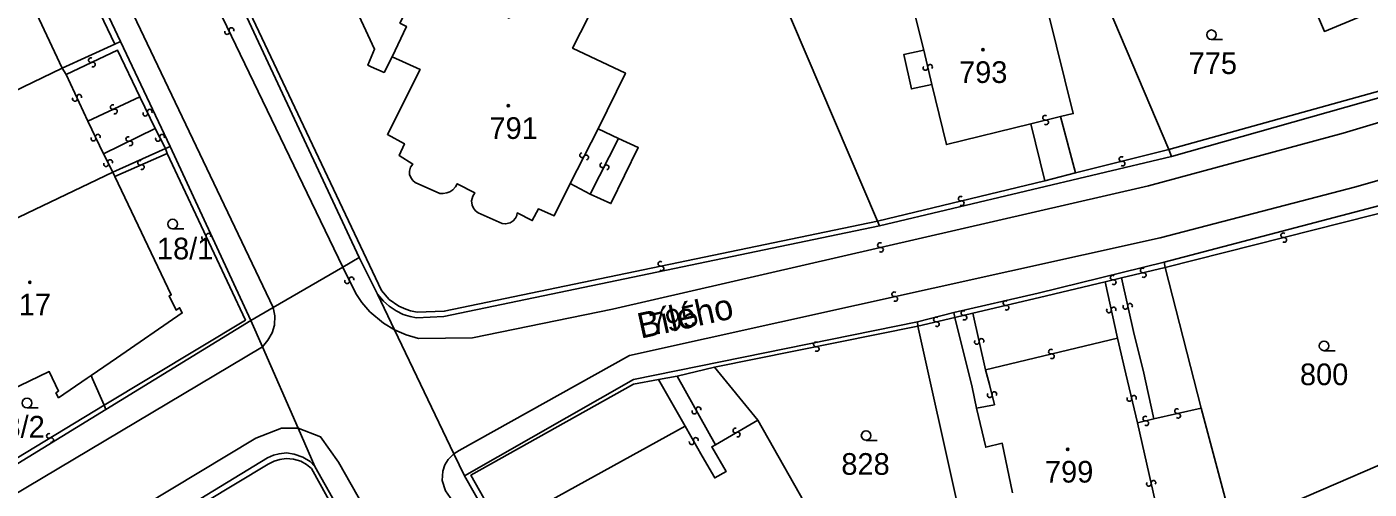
# Model space of a CAD drawing. Extents: x -600391 to -599491, y -1160176 to -1159402.
# Drawn here: x -600056.6 to -599951.3, y -1160105.5 to -1160069.3 of the extents above; entities that cross this region are included whole.
import ezdxf

# ---------------------------------------------------------------- set-up
doc = ezdxf.new("R2010")
doc.units = 0
for name, color, linetype in [('Level 1', 7, 'Continuous'), ('Level 11', 7, 'Continuous'), ('Level 13', 7, 'Continuous'), ('Level 3', 7, 'Continuous'), ('Level 4', 7, 'Continuous'), ('Level 5', 7, 'Continuous')]:
    doc.layers.add(name, color=color, linetype=linetype)

msp = doc.modelspace()

# ---------------------------------------------------------------- linework, layer by layer
at = {"layer": 'Level 1'}
for points in [[(-600006.64, -1160045.18), (-599989.86, -1160084.51)], [(-600027.94, -1160071.62), (-600028.57, -1160072.85), (-600029.57, -1160072.4), (-600029.83, -1160072.28), (-600029.31, -1160071.03), (-600033.81, -1160061.32), (-600032.1, -1160060.51), (-600032.98, -1160058.36)], [(-599958.56, -1160060.36), (-599956.78, -1160064.28), (-599957.06, -1160064.35), (-599954.81, -1160069.63), (-599951.85, -1160068.41)], [(-600053.12, -1160062.22), (-600049.24, -1160070.42)], [(-600041.96, -1160062.84), (-600030.51, -1160087.37)], [(-600025.52, -1160065.4), (-600018.76, -1160068.58), (-600017.51, -1160066.07), (-600012.52, -1160068.49), (-600013.78, -1160070.93), (-600009.63, -1160072.89), (-600011.77, -1160077.27)], [(-599986.23, -1160071.1), (-599987.04, -1160067.89), (-599977.13, -1160065.47), (-599974.51, -1160076.07), (-599975.5, -1160076.3)], [(-599972.3, -1160066.44), (-599967.02, -1160078.9)], [(-600053.82, -1160072.51), (-600049.69, -1160070.63)], [(-600049.69, -1160070.63), (-600049.24, -1160070.42)], [(-600049.24, -1160070.42), (-600045.35, -1160078.66)], [(-599966.81, -1160079.43), (-599932.7, -1160069.8)], [(-600013.97, -1160081.57), (-600015.23, -1160084.1), (-600016.46, -1160083.55), (-600016.94, -1160084.47), (-600018.12, -1160083.87), (-600018.16, -1160084.08), (-600018.26, -1160084.29), (-600018.43, -1160084.49), (-600018.67, -1160084.65), (-600019.03, -1160084.73), (-600019.31, -1160084.7), (-600021.19, -1160083.87), (-600021.4, -1160083.7), (-600021.56, -1160083.5), (-600021.66, -1160083.25), (-600021.7, -1160082.91), (-600021.61, -1160082.55), (-600021.45, -1160082.29), (-600022.83, -1160081.58), (-600022.96, -1160081.82), (-600023.18, -1160082.06), (-600023.41, -1160082.21), (-600023.63, -1160082.3), (-600023.93, -1160082.35), (-600024.18, -1160082.33), (-600026.12, -1160081.47), (-600026.32, -1160081.31), (-600026.47, -1160081.1), (-600026.56, -1160080.85), (-600026.57, -1160080.6), (-600026.48, -1160080.27), (-600026.31, -1160080.04), (-600027.38, -1160079.37), (-600026.97, -1160078.44), (-600028.3, -1160077.71), (-600025.74, -1160072.61), (-600027.94, -1160071.62)], [(-599985.6, -1160073.8), (-599987.21, -1160074.14), (-599987.8, -1160071.45), (-599986.23, -1160071.1)], [(-600065.43, -1160078.11), (-600053.82, -1160072.51)], [(-599977.85, -1160076.87), (-599984.46, -1160078.5), (-599985.6, -1160073.8)], [(-599976.74, -1160081.35), (-599977.85, -1160076.87)], [(-599975.5, -1160076.3), (-599974.33, -1160080.73)], [(-600010.17, -1160078.02), (-600008.63, -1160078.74), (-600010.77, -1160083.13), (-600012.39, -1160082.4)], [(-600011.77, -1160077.27), (-600010.17, -1160078.02)], [(-600049.84, -1160080.67), (-600045.71, -1160078.82)], [(-600045.71, -1160078.82), (-600045.35, -1160078.66)], [(-600045.35, -1160078.66), (-600039.01, -1160092.3)], [(-599967.02, -1160078.9), (-599966.81, -1160079.43)], [(-599989.71, -1160084.88), (-599966.81, -1160079.43)], [(-600060.91, -1160085.95), (-600049.84, -1160080.67)], [(-600051.55, -1160096.62), (-600049.56, -1160095.25), (-600044.39, -1160091.71), (-600044.61, -1160091.31), (-600044.88, -1160091.49), (-600045.41, -1160090.37), (-600045.26, -1160090.3), (-600049.69, -1160081.01)], [(-600049.84, -1160080.67), (-600049.69, -1160081.01)], [(-599974.33, -1160080.73), (-599976.74, -1160081.35)], [(-600012.39, -1160082.4), (-600013.97, -1160081.57)], [(-599967.37, -1160087.73), (-599948.86, -1160082.86)], [(-600029.07, -1160090.25), (-600028.62, -1160090.79), (-600028.17, -1160091.19), (-600027.62, -1160091.56), (-600027.06, -1160091.83), (-600026.53, -1160091.99), (-600026.02, -1160092.09), (-600023.89, -1160092), (-599989.71, -1160084.88)], [(-599989.86, -1160084.51), (-599989.71, -1160084.88)], [(-600031.79, -1160088.11), (-600030.51, -1160087.37)], [(-600030.51, -1160087.37), (-600029.07, -1160090.25)], [(-600037.27, -1160091.29), (-600031.79, -1160088.11)], [(-599983.88, -1160091.69), (-599977.26, -1160090.16), (-599967.37, -1160087.73)], [(-599967.37, -1160087.73), (-599967.31, -1160088.16)], [(-599967.31, -1160088.16), (-599964.48, -1160099.18)], [(-600029.07, -1160090.25), (-600027.74, -1160093.03)], [(-600064.95, -1160091.88), (-600063.13, -1160091), (-600059.45, -1160098.53), (-600054.83, -1160096.31), (-600054.09, -1160097.84), (-600054.31, -1160097.99), (-600054.09, -1160098.36), (-600051.86, -1160096.84), (-600051.55, -1160096.62)], [(-600039.01, -1160092.3), (-600037.27, -1160091.29)], [(-599986.74, -1160092.4), (-599983.88, -1160091.69)], [(-599983.88, -1160091.69), (-599983.79, -1160092.07)], [(-600050.39, -1160099.28), (-600039.01, -1160092.3)], [(-600038.1, -1160094.38), (-600039.01, -1160092.3)], [(-600022.27, -1160104.48), (-600008.99, -1160096.93), (-599986.74, -1160092.4)], [(-599986.69, -1160092.75), (-599986.74, -1160092.4)], [(-599983.59, -1160106.73), (-599986.69, -1160092.75)], [(-599983.79, -1160092.07), (-599982.44, -1160097.54), (-599982.09, -1160099.18)], [(-600027.74, -1160093.03), (-600023.09, -1160102.76)], [(-600035.3, -1160100.76), (-600038.1, -1160094.38)], [(-600051.55, -1160096.62), (-600051.44, -1160096.88), (-600050.53, -1160098.96)], [(-600007.05, -1160096.93), (-600005.57, -1160096.66)], [(-600004.95, -1160100.6), (-600007.05, -1160096.93)], [(-600005.57, -1160096.66), (-600002.65, -1160095.96)], [(-599999.26, -1160100.13), (-600002.65, -1160095.96)], [(-600050.53, -1160098.96), (-600050.39, -1160099.28)], [(-600058.81, -1160104.45), (-600050.39, -1160099.28)], [(-599999.26, -1160100.13), (-599994.78, -1160108.03), (-600000.45, -1160111.2), (-600001.17, -1160109.91), (-600010.56, -1160115.34), (-600015.61, -1160106.47), (-600004.95, -1160100.6)], [(-599982.09, -1160099.18), (-599981.37, -1160102.25), (-599980.08, -1160101.94), (-599979.27, -1160105.83)], [(-599964.48, -1160099.18), (-599961.96, -1160108.61)], [(-600033.99, -1160103.75), (-600035.3, -1160100.76)], [(-599942.6, -1160100.22), (-599961.96, -1160108.61)], [(-600047.7, -1160109.17), (-600037.71, -1160103.09), (-600037.23, -1160102.88), (-600036.8, -1160102.76), (-600036.21, -1160102.7), (-600035.62, -1160102.78), (-600034.93, -1160103.02), (-600034.37, -1160103.37), (-600033.99, -1160103.75)], [(-600023.09, -1160102.76), (-600022.27, -1160104.48)], [(-600033.99, -1160103.75), (-600015.67, -1160136.28)], [(-600011.85, -1160122.8), (-600022.27, -1160104.48)]]:
    msp.add_lwpolyline(points, dxfattribs=at)
at = {"layer": 'Level 13'}
for centre, start, end in [((-600040.88, -1160069.68), 153.1022, 25.2002), ((-600040.54, -1160069.52), 332.8878, 205.4778), ((-600051.56, -1160071.88), 62.6699, 294.7679), ((-600051.4, -1160072.22), 242.4554, 115.0454), ((-599986.1, -1160072.49), 140.5068, 12.6048), ((-599985.74, -1160072.41), 320.2923, 192.8823), ((-600052.81, -1160074.92), 151.9532, 24.5432), ((-600052.47, -1160074.76), 332.1676, 204.2656), ((-600049.84, -1160075.56), 62.5128, 294.6108), ((-600049.68, -1160075.9), 242.2984, 114.8884), ((-600046.95, -1160075.92), 333.0966, 205.1946), ((-600047.29, -1160076.08), 152.8822, 25.4722), ((-599976.72, -1160076.4), 50.7923, 283.3823), ((-599976.64, -1160076.76), 231.0067, 103.1047), ((-600051.36, -1160078.04), 152.4563, 25.0463), ((-600051.02, -1160077.88), 332.6708, 204.7688), ((-600048.63, -1160078.07), 63.4397, 296.0297), ((-600046.3, -1160078.06), 154.9653, 27.5553), ((-600045.98, -1160077.89), 335.1798, 207.2778), ((-600048.47, -1160078.41), 243.6541, 115.7521), ((-600050.37, -1160080.04), 154.5191, 27.1091), ((-600050.05, -1160079.88), 334.7335, 206.8315), ((-600047.7, -1160079.93), 61.0896, 293.1876), ((-600047.56, -1160080.27), 240.8751, 113.4651), ((-600013.03, -1160079.34), 100.0627, 332.6527), ((-600012.71, -1160079.51), 280.2772, 152.3752), ((-600011.44, -1160080.13), 100.2801, 332.8701), ((-600011.12, -1160080.29), 280.4946, 152.5926), ((-599970.72, -1160079.64), 51.213, 283.803), ((-599970.64, -1160080), 231.4274, 103.5254), ((-599983.34, -1160082.75), 50.7003, 283.2903), ((-599983.26, -1160083.11), 230.9147, 103.0127), ((-600042.68, -1160085.81), 152.2855, 24.8755), ((-600042.34, -1160085.65), 332.4999, 204.5979), ((-599989.67, -1160086.39), 50.3335, 282.4315), ((-599958.04, -1160085.62), 51.5682, 283.6661), ((-599957.96, -1160085.98), 231.3537, 103.9437), ((-599989.59, -1160086.75), 230.1191, 102.7091), ((-600006.89, -1160087.86), 48.9118, 281.5018), ((-600006.81, -1160088.22), 229.1262, 101.2242), ((-599969.06, -1160088.38), 50.6973, 282.7953), ((-599968.98, -1160088.74), 230.4828, 103.0728), ((-600031.46, -1160089.23), 152.8351, 25.4251), ((-600031.12, -1160089.07), 333.0496, 205.1475), ((-599971.42, -1160088.94), 50.8853, 282.9833), ((-599971.34, -1160089.3), 230.6708, 103.2608), ((-599988.55, -1160090.25), 49.6492, 282.2392), ((-599988.47, -1160090.61), 229.8636, 101.9616), ((-599983.13, -1160091.72), 51.0232, 283.1212), ((-599979.82, -1160090.94), 50.6316, 282.7296), ((-599979.74, -1160091.3), 230.4172, 103.0072), ((-599971.71, -1160091.52), 139.9015, 11.9995), ((-599971.35, -1160091.44), 319.6871, 192.2771), ((-599970.42, -1160091.23), 139.9425, 12.0405), ((-599970.06, -1160091.15), 319.7281, 192.3181), ((-599985.28, -1160092.23), 50.5692, 282.6672), ((-599985.2, -1160092.59), 230.3547, 102.9447), ((-599983.05, -1160092.08), 230.8087, 103.3987), ((-599981.71, -1160093.91), 320.0654, 192.1634), ((-599994.7, -1160094.18), 48.7448, 280.8428), ((-599994.63, -1160094.54), 228.5303, 101.1203), ((-599982.07, -1160093.99), 139.8509, 12.4409), ((-599976.26, -1160094.75), 50.8475, 282.9455), ((-599976.18, -1160095.11), 230.6331, 103.2231), ((-599980.7, -1160098.08), 320.9399, 193.5299), ((-600003.91, -1160099.27), 336.1768, 208.7668), ((-599981.06, -1160098.16), 141.1543, 13.2523), ((-599970.11, -1160098.46), 140.5238, 13.1138), ((-599969.75, -1160098.38), 320.7383, 192.8363), ((-600004.23, -1160099.45), 156.3912, 28.4892), ((-599968.86, -1160100), 50.2502, 282.8402), ((-599966.37, -1160099.42), 50.0963, 282.6863), ((-599966.29, -1160099.78), 230.3108, 102.4088), ((-600054.85, -1160101.36), 68.291, 300.881), ((-600001.01, -1160100.93), 67.1996, 299.7896), ((-600000.83, -1160101.25), 247.4141, 119.5121), ((-599968.78, -1160100.36), 230.4646, 102.5626), ((-600054.67, -1160101.68), 248.5055, 120.6035), ((-600004.44, -1160101.86), 156.8506, 29.4406), ((-600004.12, -1160101.68), 337.0651, 209.1631), ((-599968.58, -1160105.12), 139.9104, 12.5004), ((-599968.22, -1160105.04), 320.1249, 192.2229)]:
    msp.add_arc(centre, 0.184, start, end, dxfattribs=at)
at = {"layer": 'Level 3'}
for points in [[(-600037.27, -1160091.29), (-600057.56, -1160048.75), (-600077.92, -1160005.83), (-600078.21, -1160005.38), (-600078.52, -1160005.04), (-600078.89, -1160004.78), (-600079.31, -1160004.57), (-600079.97, -1160004.4), (-600080.6, -1160004.42)], [(-600031.79, -1160088.11), (-600049.63, -1160051.09), (-600056.12, -1160037.4), (-600056.33, -1160036.93), (-600056.42, -1160036.47), (-600056.41, -1160035.97), (-600056.25, -1160035.39), (-600055.93, -1160034.88), (-600055.58, -1160034.55), (-600055.38, -1160034.38)], [(-599967.02, -1160078.9), (-599933.24, -1160069.5), (-599940.38, -1160052.87)], [(-600057.43, -1160064.8), (-600053.38, -1160062.9), (-600049.69, -1160070.63)], [(-599989.86, -1160084.51), (-600023.84, -1160091.58), (-600025.96, -1160091.65), (-600026.48, -1160091.54), (-600026.86, -1160091.42), (-600027.4, -1160091.19), (-600028.16, -1160090.66), (-600028.78, -1160089.96), (-600041.68, -1160062.64)], [(-600057.43, -1160064.8), (-600053.82, -1160072.51)], [(-600027.94, -1160071.62), (-600026.81, -1160069.24), (-600027.32, -1160068.98), (-600025.52, -1160065.4)], [(-600053.49, -1160073), (-600049.47, -1160071.1), (-600047.72, -1160074.77)], [(-600027.74, -1160093.03), (-600026.82, -1160093.42), (-600025.86, -1160093.71), (-600021.64, -1160093.67), (-600010.66, -1160091.41), (-599968.6, -1160081.73), (-599953.35, -1160077.6), (-599932.07, -1160071.24)], [(-599985.6, -1160073.8), (-599986.23, -1160071.1)], [(-600053.82, -1160072.51), (-600053.49, -1160073)], [(-600053.49, -1160073), (-600051.79, -1160076.68)], [(-600051.79, -1160076.68), (-600047.72, -1160074.77)], [(-600047.72, -1160074.77), (-600046.53, -1160077.24)], [(-599930.21, -1160075.52), (-599930.99, -1160075.71), (-599952.34, -1160081.82), (-599967.7, -1160085.82), (-600009.32, -1160095.04), (-600022.67, -1160102.5), (-600023.09, -1160102.76)], [(-600051.79, -1160076.68), (-600050.58, -1160079.24)], [(-599975.5, -1160076.3), (-599977.85, -1160076.87)], [(-600046.53, -1160077.24), (-600050.58, -1160079.24)], [(-600046.53, -1160077.24), (-600045.76, -1160078.7), (-600045.71, -1160078.82)], [(-600011.77, -1160077.27), (-600013.97, -1160081.57)], [(-600010.17, -1160078.02), (-600012.39, -1160082.4)], [(-600045.71, -1160078.82), (-600045.57, -1160079.2)], [(-599967.02, -1160078.9), (-599974.33, -1160080.73)], [(-600050.58, -1160079.24), (-600049.84, -1160080.67)], [(-600045.57, -1160079.2), (-600039.44, -1160092.27), (-600050.53, -1160098.96)], [(-600049.69, -1160081.01), (-600045.57, -1160079.2)], [(-599976.74, -1160081.35), (-599989.86, -1160084.51)], [(-599967.31, -1160088.16), (-599948.69, -1160083.45)], [(-600031.79, -1160088.11), (-600030.79, -1160090.19), (-600030.3, -1160090.9), (-600029.67, -1160091.62), (-600028.6, -1160092.51), (-600027.74, -1160093.03)], [(-599970.73, -1160088.97), (-599967.31, -1160088.16)], [(-599982.39, -1160091.73), (-599977.17, -1160090.5), (-599972.02, -1160089.28)], [(-599972.02, -1160089.28), (-599970.73, -1160088.97)], [(-599971.04, -1160093.69), (-599972.02, -1160089.28)], [(-599968.18, -1160100.03), (-599969.04, -1160096.21), (-599969.74, -1160093.41), (-599970.73, -1160088.97)], [(-600037.27, -1160091.29), (-600037.13, -1160091.93), (-600037.17, -1160092.67), (-600037.35, -1160093.27), (-600037.67, -1160093.86), (-600038.1, -1160094.38)], [(-600002.65, -1160095.96), (-599986.69, -1160092.75)], [(-599986.69, -1160092.75), (-599983.79, -1160092.07)], [(-599983.79, -1160092.07), (-599982.39, -1160091.73)], [(-599982.39, -1160091.73), (-599981.39, -1160096.17)], [(-599981.39, -1160096.17), (-599971.04, -1160093.69)], [(-599971.04, -1160093.69), (-599970.38, -1160096.5), (-599969.47, -1160100.33)], [(-600038.1, -1160094.38), (-600078.93, -1160118.69), (-600104.94, -1160134.34), (-600126.03, -1160147.1), (-600155.88, -1160165.42)], [(-600011.5, -1160122.58), (-600021.76, -1160104.45), (-600009, -1160097.3), (-600007.05, -1160096.93)], [(-600002.58, -1160102.05), (-600005.57, -1160096.66)], [(-599982.09, -1160099.18), (-599980.69, -1160098.92), (-599981.08, -1160097.33), (-599981.39, -1160096.17)], [(-600050.53, -1160098.96), (-600058.99, -1160104.07)], [(-599999.26, -1160100.13), (-600002.58, -1160102.05)], [(-599968.18, -1160100.03), (-599969.47, -1160100.33)], [(-599964.48, -1160099.18), (-599968.18, -1160100.03)], [(-600035.3, -1160100.76), (-600036.62, -1160100.76), (-600038.63, -1160101.53), (-600104, -1160140.93), (-600152.12, -1160170.19)], [(-600035.3, -1160100.76), (-600033.55, -1160101.43), (-600032.15, -1160103.43), (-600003.04, -1160154.73), (-599996.06, -1160167.09), (-599995.71, -1160167.83), (-599995.54, -1160168.65), (-599995.53, -1160169.34), (-599995.66, -1160170.19), (-599996.01, -1160171)], [(-600004.95, -1160100.6), (-600003.61, -1160102.95), (-600002.63, -1160104.65), (-600001.74, -1160104.16), (-600002.86, -1160102.21), (-600002.58, -1160102.05)], [(-599969.47, -1160100.33), (-599967.32, -1160109.83)], [(-600047.52, -1160109.52), (-600037.65, -1160103.57), (-600037.18, -1160103.33), (-600036.75, -1160103.2), (-600036.25, -1160103.14), (-600035.68, -1160103.18), (-600035.1, -1160103.35), (-600034.65, -1160103.6), (-600034.26, -1160103.91), (-600031.11, -1160109.58)], [(-599983.69, -1160176.08), (-599996.95, -1160152.06), (-600023.38, -1160106.19), (-600023.76, -1160105.67), (-600024, -1160104.87), (-600023.96, -1160104.12), (-600023.8, -1160103.64), (-600023.54, -1160103.22), (-600023.09, -1160102.76)]]:
    msp.add_lwpolyline(points, dxfattribs=at)
at = {"layer": 'Level 5'}
for p, q in [((-599963.67, -1160070.27), (-599962.8, -1160070.27)), ((-600045.15, -1160085.12), (-600044.28, -1160085.12)), ((-599954.84, -1160094.68), (-599953.96, -1160094.68)), ((-600056.57, -1160099.16), (-600055.7, -1160099.16)), ((-599990.76, -1160101.71), (-599989.89, -1160101.71))]:
    msp.add_line(p, q, dxfattribs=at)
for centre, radius in [((-599963.67, -1160069.89), 0.375), ((-599981.6, -1160071.07), 0.09), ((-599981.6, -1160071.07), 0.0521), ((-600018.82, -1160075.46), 0.09), ((-600018.82, -1160075.46), 0.0521), ((-600045.15, -1160084.74), 0.375), ((-600056.35, -1160089.31), 0.09), ((-600056.35, -1160089.31), 0.0521), ((-599954.84, -1160094.3), 0.375), ((-600056.57, -1160098.78), 0.375), ((-599990.76, -1160101.33), 0.375), ((-599974.94, -1160102.42), 0.09), ((-599974.94, -1160102.42), 0.0521)]:
    msp.add_circle(centre, radius, dxfattribs=at)

# ---------------------------------------------------------------- texts
at = {"layer": 'Level 11'}
msp.add_text('Bílého', height=2, rotation=12.3997, dxfattribs=at).set_placement((-600008.44, -1160093.74))
at = {"layer": 'Level 4'}
for s, p in [('775', (-599965.46, -1160072.97)), ('793', (-599983.47, -1160073.67)), ('791', (-600020.3, -1160078.06)), ('18/1', (-600046.38, -1160087.51)), ('17', (-600057.22, -1160091.91)), ('800', (-599956.73, -1160097.38)), ('18/2', (-600059.6, -1160101.49)), ('828', (-599992.7, -1160104.41)), ('799', (-599976.73, -1160105.02))]:
    msp.add_text(s, height=1.7, dxfattribs=at).set_placement(p)
msp.add_text('795', height=1.7, rotation=12.6, dxfattribs=at).set_placement((-600007.51, -1160093.48))

doc.saveas('drawing.dxf')
